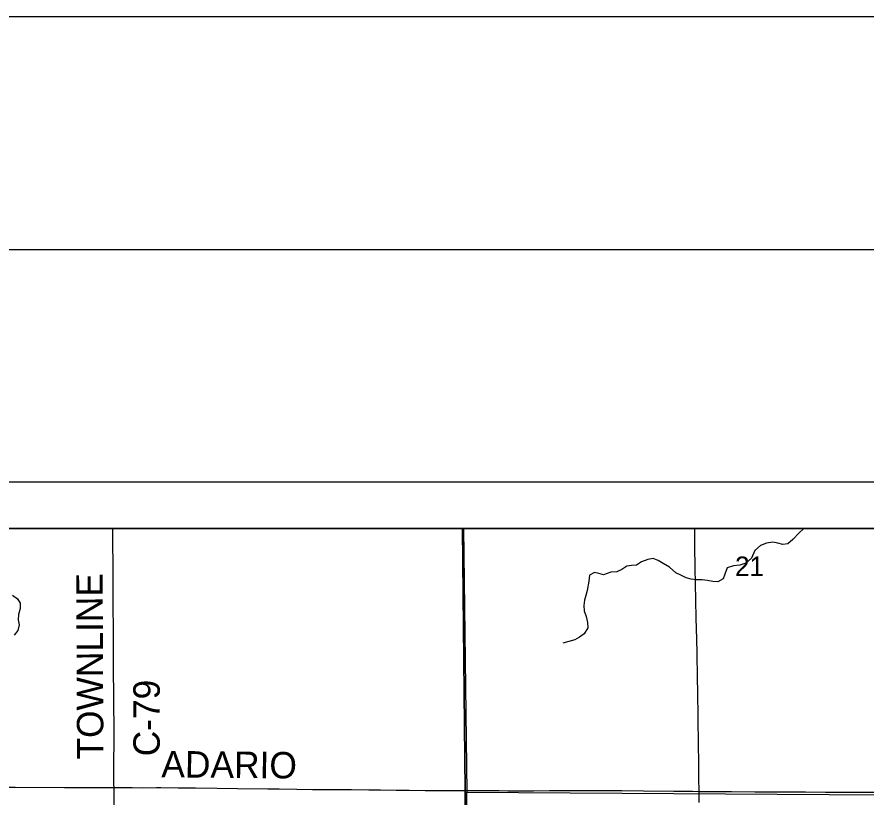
# Model space of a CAD drawing. Extents: x 0 to 70.2, y 0 to 31.4.
# Drawn here: x 5.776 to 7.601, y 20.322 to 22 of the extents above; entities that cross this region are included whole.
import ezdxf

# ---------------------------------------------------------------- set-up
doc = ezdxf.new("R2010")
doc.units = 0
for name, color, linetype in [('GM_X_County_Road', 7, 'Continuous'), ('GM_X_County_Road_Text', 7, 'Continuous'), ('GM_X_Minor_River', 7, 'Continuous'), ('GM_X_Section', 7, 'Continuous'), ('GM_X_Section_Text', 7, 'Continuous'), ('GM_X_State_Route', 7, 'Continuous'), ('GM_X_Township_Road', 7, 'Continuous'), ('SH_Border', 7, 'Continuous'), ('SH_Cut_Line', 7, 'Continuous'), ('SH_Data', 7, 'Continuous')]:
    doc.layers.add(name, color=color, linetype=linetype)

msp = doc.modelspace()

# ---------------------------------------------------------------- linework, layer by layer
at = {"layer": 'GM_X_County_Road'}
for points in [[(5.9848, 20.3424), (5.9844, 20.3494), (5.9845, 20.3714), (5.9849, 20.467), (5.9844, 20.5259), (5.9838, 20.6098), (5.9836, 20.6782), (5.9832, 20.7372), (5.983, 20.79), (5.9821, 20.9)], [(5.638, 20.3441), (5.6825, 20.3436), (5.7353, 20.3437), (5.7726, 20.3433), (5.8783, 20.343), (5.9498, 20.3425), (5.9848, 20.3424)], [(5.9848, 20.3424), (6.0236, 20.3424), (6.0454, 20.3423), (6.0764, 20.3425), (6.0857, 20.3426), (6.1229, 20.3422), (6.1602, 20.342), (6.2067, 20.3412), (6.2502, 20.3406), (6.3154, 20.3401), (6.3402, 20.3399), (6.3775, 20.3392), (6.4116, 20.3387), (6.4644, 20.3383), (6.4954, 20.3381), (6.5327, 20.3376), (6.5575, 20.3374), (6.5917, 20.3369), (6.6196, 20.3368), (6.6538, 20.3366), (6.7397, 20.336)]]:
    msp.add_lwpolyline(points, dxfattribs=at)
at = {"layer": 'GM_X_Minor_River'}
for points in [[(7.4682, 20.9), (7.4673, 20.8993), (7.4574, 20.8906), (7.4441, 20.8762), (7.4335, 20.8667), (7.4229, 20.8652), (7.4119, 20.8683), (7.4013, 20.8705), (7.3876, 20.8683), (7.3743, 20.8633), (7.3622, 20.8524), (7.3554, 20.836), (7.3432, 20.825), (7.3303, 20.8209), (7.3167, 20.8194), (7.303, 20.8152), (7.2981, 20.8016), (7.2943, 20.7917), (7.2829, 20.7849), (7.2719, 20.786), (7.2609, 20.7879), (7.2495, 20.7891), (7.2366, 20.7891), (7.2253, 20.7906), (7.2146, 20.794), (7.2033, 20.7993), (7.1926, 20.8047), (7.179, 20.8164), (7.165, 20.8248), (7.1544, 20.8312), (7.1441, 20.835), (7.1327, 20.8331), (7.1187, 20.8282), (7.1081, 20.821), (7.0971, 20.8199), (7.0872, 20.8188), (7.0766, 20.8119), (7.0656, 20.8066), (7.0527, 20.8055), (7.0371, 20.8002), (7.0273, 20.8029), (7.0178, 20.8048), (7.0072, 20.7991), (7.0053, 20.7862), (7.0022, 20.7661), (6.9988, 20.7558), (6.9962, 20.7456), (6.995, 20.7342), (6.9958, 20.7225), (6.9999, 20.7103), (7.003, 20.6974), (7.0037, 20.6864), (6.9954, 20.6731), (6.9851, 20.6659), (6.9753, 20.6606), (6.9627, 20.6565), (6.9498, 20.6534)], [(5.7666, 20.7565), (5.7772, 20.7488), (5.7832, 20.7393), (5.7832, 20.7275), (5.7797, 20.715), (5.7785, 20.7033), (5.7807, 20.6926), (5.778, 20.6801), (5.77, 20.6703)]]:
    msp.add_lwpolyline(points, dxfattribs=at)
at = {"layer": 'GM_X_Section'}
msp.add_lwpolyline([(7.7445, 20.3265), (7.76, 19.3074), (6.7477, 19.3154), (6.7432, 20.333)], close=True, dxfattribs=at)
at = {"layer": 'GM_X_Section_Text'}
for points in [[(5.7517, 18.3204), (6.7461, 18.306), (6.749, 19.3206), (6.7395, 20.3365), (6.7343, 20.9), (2.6577, 20.9)], [(8.9, 20.9), (6.7343, 20.9), (6.7395, 20.3365), (6.749, 19.3206), (6.7461, 18.306), (6.7742, 18.3058), (6.8676, 18.3057), (7.2705, 18.3155), (7.2966, 18.3153), (7.3494, 18.3155), (7.3774, 18.3154), (7.4209, 18.3155), (7.4458, 18.3156), (7.4645, 18.3154), (7.5173, 18.3158), (7.5515, 18.3159), (7.5981, 18.3162), (7.6197, 18.3167)]]:
    msp.add_lwpolyline(points, dxfattribs=at)
at = {"layer": 'GM_X_State_Route'}
msp.add_lwpolyline([(7.7382, 20.9), (6.7361, 20.9), (6.7432, 20.333), (7.7445, 20.3265)], close=True, dxfattribs=at)
at = {"layer": 'GM_X_Township_Road'}
for points in [[(7.2425, 20.3344), (7.2422, 20.3631), (7.2418, 20.3973), (7.2413, 20.4346), (7.2397, 20.5495), (7.2393, 20.5775), (7.2383, 20.6334), (7.2377, 20.6613), (7.2364, 20.7079), (7.2357, 20.7452), (7.2348, 20.7824), (7.2343, 20.8135), (7.2337, 20.8632), (7.2334, 20.9)], [(5.9882, 19.8293), (5.9876, 19.8411), (5.9873, 19.85), (5.9869, 19.8697), (5.9866, 19.9007), (5.9867, 19.9685), (5.9866, 19.9969), (5.9863, 20.0742), (5.9864, 20.1236), (5.986, 20.1684), (5.986, 20.1914), (5.986, 20.2245), (5.9856, 20.2498), (5.9854, 20.2709), (5.9854, 20.291), (5.9852, 20.3108), (5.9852, 20.3347), (5.9848, 20.3424)], [(6.7397, 20.336), (6.7536, 20.3361), (6.7847, 20.336), (6.8126, 20.3359), (6.8312, 20.3356), (6.8652, 20.3357), (6.8745, 20.3357), (6.8869, 20.3357), (6.9211, 20.336), (6.9615, 20.3361), (7.005, 20.3362), (7.0516, 20.336), (7.0764, 20.3362), (7.123, 20.3358), (7.1882, 20.3351), (7.2286, 20.3346), (7.2425, 20.3344)], [(7.2425, 20.3344), (7.2535, 20.3343), (7.3125, 20.3341), (7.3622, 20.3336), (7.3964, 20.3335), (7.443, 20.3336), (7.471, 20.3335), (7.5145, 20.333), (7.5549, 20.333), (7.6263, 20.3325), (7.6698, 20.3322), (7.7009, 20.332), (7.7288, 20.3319), (7.7475, 20.3321), (7.7599, 20.3323), (7.7847, 20.3325), (7.8158, 20.3324), (7.8686, 20.3328), (7.8997, 20.3328), (7.9121, 20.3326), (7.9227, 20.3323)], [(7.2427, 20.3103), (7.2425, 20.332), (7.2425, 20.3344)]]:
    msp.add_lwpolyline(points, dxfattribs=at)
at = {"layer": 'SH_Border'}
msp.add_lwpolyline([(1.5, 21.5), (33.5, 21.5), (33.5, 0.5), (1.5, 0.5)], close=True, dxfattribs=at)
at = {"layer": 'SH_Cut_Line'}
msp.add_lwpolyline([(0, 0), (34, 0), (34, 22), (0, 22)], close=True, dxfattribs=at)
for points in [[(6.7786, 18.1369), (6.7742, 18.3058), (6.7461, 18.306), (6.749, 19.3206), (6.7395, 20.3365), (6.7343, 20.9), (2.1, 20.9), (2.1, 14.1)], [(8.9, 14.1), (8.9, 20.9), (6.7343, 20.9), (6.7395, 20.3365), (6.749, 19.3206), (6.7461, 18.306), (6.7742, 18.3058), (6.7786, 18.1369)]]:
    msp.add_lwpolyline(points, dxfattribs=at)
at = {"layer": 'SH_Data'}
for p, q in [((2, 21), (9, 21)), ((2.1, 20.9), (8.9, 20.9))]:
    msp.add_line(p, q, dxfattribs=at)

# ---------------------------------------------------------------- texts
at = {"layer": 'GM_X_County_Road_Text'}
for s, rotation, p in [('TOWNLINE', 90.2595, (5.9622, 20.403)), ('C-79', 90, (6.0832, 20.4098)), ('ADARIO', 359.4732, (6.0864, 20.3647))]:
    msp.add_text(s, height=0.05682, rotation=rotation, dxfattribs=at).set_placement(p)
at = {"layer": 'GM_X_Section_Text'}
msp.add_text('21', height=0.04186, rotation=0, dxfattribs=at).set_placement((7.3198, 20.7977))

doc.saveas('drawing.dxf')
